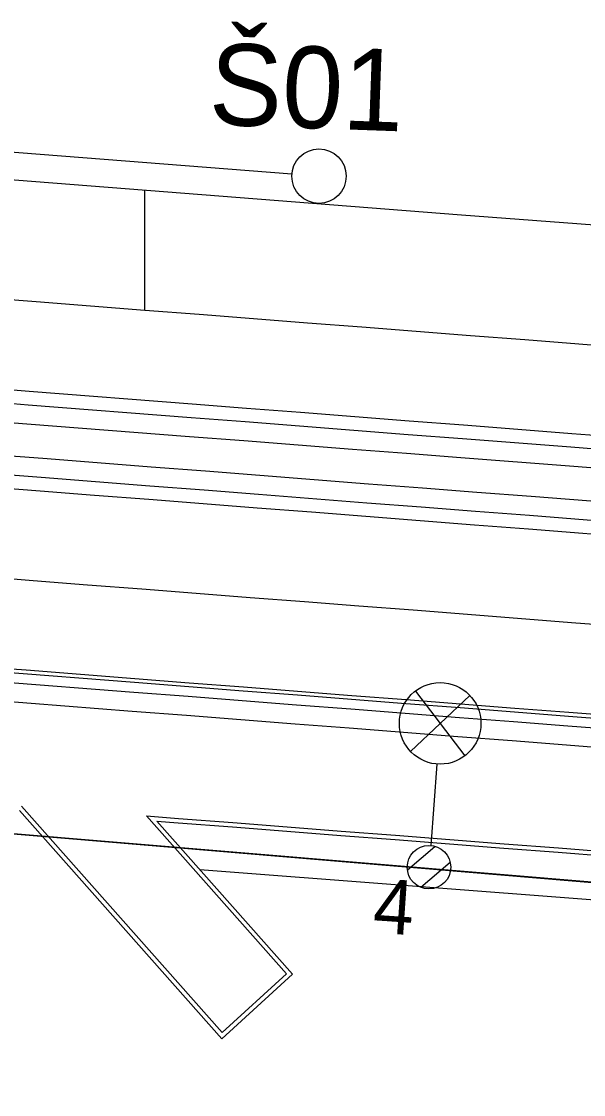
# Model space of a CAD drawing. Extents: x -669628 to -669207, y -977198 to -977075.
# Drawn here: x -669500.74 to -669490.41, y -977152.98 to -977133.27 of the extents above; entities that cross this region are included whole.
import ezdxf

# ---------------------------------------------------------------- set-up
doc = ezdxf.new("R2010")
doc.units = 0
for name, color, linetype in [('SO 01-86-01', 7, 'Continuous'), ('SO 11-10-01', 7, 'Continuous'), ('SO 11-11-01', 7, 'Continuous'), ('SO 11-12-01', 7, 'Continuous'), ('SO 11-12-02', 7, 'Continuous')]:
    doc.layers.add(name, color=color, linetype=linetype)

# ---------------------------------------------------------------- blocks, each defined once
blk = doc.blocks.new('POINT_DISPLAY')
blk.add_line((0, 0), (0, 0))

msp = doc.modelspace()

# ---------------------------------------------------------------- linework, layer by layer
at = {"layer": 'SO 01-86-01'}
for p, q in [((-669519.163, -977134.751), (-669492.657, -977136.821)), ((-669498.473, -977138.568), (-669498.473, -977136.368)), ((-669492.657, -977136.821), (-669476.036, -977138.048)), ((-669493.503, -977145.567), (-669492.591, -977146.754)), ((-669493.589, -977146.676), (-669492.504, -977145.645)), ((-669445.341, -977152.857), (-669517.763, -977146.78)), ((-669445.341, -977152.857), (-669517.763, -977146.78)), ((-669443.485, -977152.976), (-669517.763, -977146.78)), ((-669493.105, -977146.907), (-669493.221, -977148.402)), ((-669493.646, -977148.851), (-669493.142, -977148.419)), ((-669493.402, -977149.167), (-669492.865, -977148.708))]:
    msp.add_line(p, q, dxfattribs=at)
for centre, radius in [((-669493.047, -977146.16), 0.749), ((-669493.252, -977148.801), 0.4)]:
    msp.add_circle(centre, radius, dxfattribs=at)
at = {"layer": 'SO 11-10-01'}
for p, q in [((-669501.464, -977138.335), (-669500.467, -977138.413)), ((-669500.467, -977138.413), (-669499.47, -977138.491)), ((-669499.47, -977138.491), (-669498.473, -977138.568)), ((-669498.473, -977138.568), (-669497.476, -977138.646)), ((-669497.476, -977138.646), (-669496.479, -977138.723)), ((-669496.479, -977138.723), (-669495.482, -977138.801)), ((-669495.482, -977138.801), (-669494.485, -977138.879)), ((-669494.485, -977138.879), (-669493.488, -977138.956)), ((-669493.488, -977138.956), (-669492.491, -977139.034)), ((-669492.491, -977139.034), (-669491.494, -977139.111)), ((-669491.494, -977139.111), (-669490.497, -977139.189)), ((-669490.497, -977139.189), (-669489.692, -977139.252)), ((-669501.52, -977143.457), (-669500.523, -977143.534)), ((-669500.523, -977143.534), (-669499.526, -977143.612)), ((-669499.526, -977143.612), (-669498.529, -977143.689)), ((-669498.529, -977143.689), (-669497.532, -977143.767)), ((-669497.532, -977143.767), (-669496.535, -977143.845)), ((-669496.535, -977143.845), (-669495.538, -977143.922)), ((-669495.538, -977143.922), (-669494.541, -977144)), ((-669494.541, -977144), (-669493.544, -977144.077)), ((-669493.544, -977144.077), (-669492.547, -977144.155)), ((-669492.547, -977144.155), (-669491.55, -977144.233)), ((-669491.55, -977144.233), (-669490.553, -977144.31)), ((-669490.553, -977144.31), (-669489.556, -977144.388))]:
    msp.add_line(p, q, dxfattribs=at)
at = {"layer": 'SO 11-11-01'}
msp.add_line((-669495.771, -977136.07), (-669530.167, -977133.393), dxfattribs=at)
msp.add_circle((-669495.273, -977136.109), 0.5, dxfattribs=at)
at = {"layer": 'SO 11-12-01'}
for p, q in [((-669501.592, -977139.98), (-669500.595, -977140.058)), ((-669500.595, -977140.058), (-669497.604, -977140.291)), ((-669501.612, -977140.23), (-669500.615, -977140.307)), ((-669500.615, -977140.307), (-669497.624, -977140.54)), ((-669497.604, -977140.291), (-669496.607, -977140.368)), ((-669496.607, -977140.368), (-669495.61, -977140.446)), ((-669495.61, -977140.446), (-669494.613, -977140.524)), ((-669501.639, -977140.579), (-669500.642, -977140.656)), ((-669500.642, -977140.656), (-669497.651, -977140.889)), ((-669497.624, -977140.54), (-669496.627, -977140.618)), ((-669496.627, -977140.618), (-669495.63, -977140.695)), ((-669494.613, -977140.524), (-669493.616, -977140.601)), ((-669493.616, -977140.601), (-669492.619, -977140.679)), ((-669495.63, -977140.695), (-669494.633, -977140.773)), ((-669494.633, -977140.773), (-669493.636, -977140.851)), ((-669493.636, -977140.851), (-669492.639, -977140.928)), ((-669492.619, -977140.679), (-669491.622, -977140.757)), ((-669491.622, -977140.757), (-669490.625, -977140.834)), ((-669490.625, -977140.834), (-669489.82, -977140.897)), ((-669497.651, -977140.889), (-669496.654, -977140.967)), ((-669496.654, -977140.967), (-669495.657, -977141.044)), ((-669495.657, -977141.044), (-669494.66, -977141.122)), ((-669492.639, -977140.928), (-669490.645, -977141.083)), ((-669501.345, -977141.213), (-669500.348, -977141.291)), ((-669494.66, -977141.122), (-669493.663, -977141.199)), ((-669493.663, -977141.199), (-669492.666, -977141.277)), ((-669490.645, -977141.083), (-669489.839, -977141.146)), ((-669500.348, -977141.291), (-669499.351, -977141.369)), ((-669499.351, -977141.369), (-669498.354, -977141.446)), ((-669498.354, -977141.446), (-669497.357, -977141.524)), ((-669492.666, -977141.277), (-669490.672, -977141.432)), ((-669490.672, -977141.432), (-669489.867, -977141.495)), ((-669501.372, -977141.562), (-669500.375, -977141.64)), ((-669500.375, -977141.64), (-669499.378, -977141.717)), ((-669497.357, -977141.524), (-669496.36, -977141.601)), ((-669496.36, -977141.601), (-669494.366, -977141.757)), ((-669501.392, -977141.812), (-669500.395, -977141.889)), ((-669499.378, -977141.717), (-669498.381, -977141.795)), ((-669498.381, -977141.795), (-669497.384, -977141.873)), ((-669494.366, -977141.757), (-669493.369, -977141.834)), ((-669493.369, -977141.834), (-669492.372, -977141.912)), ((-669500.395, -977141.889), (-669499.398, -977141.967)), ((-669499.398, -977141.967), (-669498.401, -977142.044)), ((-669497.384, -977141.873), (-669496.387, -977141.95)), ((-669496.387, -977141.95), (-669494.394, -977142.106)), ((-669492.372, -977141.912), (-669491.375, -977141.989)), ((-669491.375, -977141.989), (-669489.381, -977142.145)), ((-669498.401, -977142.044), (-669497.404, -977142.122)), ((-669497.404, -977142.122), (-669496.407, -977142.2)), ((-669496.407, -977142.2), (-669495.41, -977142.277)), ((-669494.394, -977142.106), (-669493.397, -977142.183)), ((-669493.397, -977142.183), (-669492.4, -977142.261)), ((-669495.41, -977142.277), (-669494.413, -977142.355)), ((-669494.413, -977142.355), (-669493.416, -977142.432)), ((-669493.416, -977142.432), (-669492.419, -977142.51)), ((-669492.4, -977142.261), (-669491.403, -977142.338)), ((-669491.403, -977142.338), (-669489.409, -977142.494)), ((-669492.419, -977142.51), (-669491.422, -977142.588)), ((-669491.422, -977142.588), (-669490.425, -977142.665)), ((-669490.425, -977142.665), (-669489.428, -977142.743)), ((-669501.653, -977145.171), (-669498.662, -977145.404)), ((-669501.648, -977145.102), (-669500.651, -977145.179)), ((-669500.651, -977145.179), (-669499.654, -977145.257)), ((-669501.667, -977145.351), (-669498.676, -977145.584)), ((-669499.654, -977145.257), (-669498.657, -977145.334)), ((-669498.657, -977145.334), (-669497.66, -977145.412)), ((-669498.676, -977145.584), (-669497.679, -977145.661)), ((-669498.662, -977145.404), (-669497.665, -977145.482)), ((-669497.665, -977145.482), (-669496.668, -977145.559)), ((-669497.66, -977145.412), (-669496.663, -977145.49)), ((-669496.668, -977145.559), (-669495.671, -977145.637)), ((-669496.663, -977145.49), (-669495.666, -977145.567)), ((-669495.666, -977145.567), (-669494.669, -977145.645)), ((-669501.694, -977145.7), (-669498.704, -977145.933)), ((-669497.679, -977145.661), (-669496.682, -977145.739)), ((-669496.682, -977145.739), (-669495.685, -977145.816)), ((-669495.671, -977145.637), (-669494.674, -977145.715)), ((-669494.674, -977145.715), (-669493.677, -977145.792)), ((-669494.669, -977145.645), (-669493.672, -977145.722)), ((-669493.672, -977145.722), (-669492.675, -977145.8)), ((-669498.704, -977145.933), (-669497.707, -977146.01)), ((-669495.685, -977145.816), (-669494.688, -977145.894)), ((-669494.688, -977145.894), (-669493.691, -977145.972)), ((-669493.691, -977145.972), (-669492.694, -977146.049)), ((-669493.677, -977145.792), (-669492.68, -977145.87)), ((-669492.68, -977145.87), (-669491.684, -977145.947)), ((-669492.675, -977145.8), (-669491.678, -977145.878)), ((-669491.684, -977145.947), (-669490.687, -977146.025)), ((-669491.678, -977145.878), (-669490.681, -977145.955)), ((-669490.681, -977145.955), (-669489.684, -977146.033)), ((-669497.707, -977146.01), (-669496.71, -977146.088)), ((-669496.71, -977146.088), (-669495.713, -977146.165)), ((-669495.713, -977146.165), (-669494.716, -977146.243)), ((-669492.694, -977146.049), (-669491.697, -977146.127)), ((-669491.697, -977146.127), (-669490.7, -977146.204)), ((-669490.687, -977146.025), (-669489.69, -977146.103)), ((-669494.716, -977146.243), (-669493.719, -977146.321)), ((-669493.719, -977146.321), (-669492.722, -977146.398)), ((-669490.7, -977146.204), (-669489.704, -977146.282)), ((-669492.722, -977146.398), (-669491.725, -977146.476)), ((-669491.725, -977146.476), (-669490.728, -977146.553)), ((-669490.728, -977146.553), (-669489.731, -977146.631)), ((-669498.442, -977147.859), (-669497.854, -977147.904)), ((-669497.854, -977147.904), (-669496.857, -977147.982)), ((-669498.251, -977147.954), (-669497.86, -977147.984)), ((-669497.86, -977147.984), (-669496.863, -977148.062)), ((-669496.863, -977148.062), (-669495.866, -977148.139)), ((-669496.857, -977147.982), (-669495.86, -977148.06)), ((-669495.866, -977148.139), (-669494.869, -977148.217)), ((-669495.86, -977148.06), (-669494.863, -977148.137)), ((-669494.863, -977148.137), (-669493.866, -977148.215)), ((-669494.869, -977148.217), (-669493.872, -977148.295)), ((-669493.872, -977148.295), (-669492.875, -977148.372)), ((-669493.866, -977148.215), (-669492.869, -977148.292)), ((-669492.869, -977148.292), (-669491.872, -977148.37)), ((-669492.875, -977148.372), (-669491.878, -977148.45)), ((-669491.878, -977148.45), (-669490.881, -977148.527)), ((-669491.872, -977148.37), (-669490.875, -977148.448)), ((-669490.881, -977148.527), (-669489.884, -977148.605)), ((-669490.875, -977148.448), (-669489.878, -977148.525)), ((-669497.465, -977148.84), (-669480.094, -977150.182))]:
    msp.add_line(p, q, dxfattribs=at)
at = {"layer": 'SO 11-12-02'}
for p, q in [((-669497.053, -977151.836), (-669500.74, -977147.68)), ((-669497.059, -977151.95), (-669500.778, -977147.757)), ((-669495.87, -977150.759), (-669498.442, -977147.859)), ((-669495.757, -977150.765), (-669498.251, -977147.954)), ((-669497.059, -977151.95), (-669495.757, -977150.765)), ((-669497.053, -977151.836), (-669495.87, -977150.759))]:
    msp.add_line(p, q, dxfattribs=at)

# ---------------------------------------------------------------- block references
at = {"layer": 'SO 01-86-01', "rotation": -4.450857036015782}
msp.add_blockref('POINT_DISPLAY', (-669493.252, -977148.801), dxfattribs=at)

# ---------------------------------------------------------------- texts
at = {"layer": 'SO 01-86-01'}
msp.add_text('4', height=1, rotation=356.1, dxfattribs=at).set_placement((-669494.3, -977150))
at = {"layer": 'SO 11-11-01'}
msp.add_text('Š01', height=1.5, rotation=357.9449, dxfattribs=at).set_placement((-669497.309, -977135.16))

doc.saveas('drawing.dxf')
